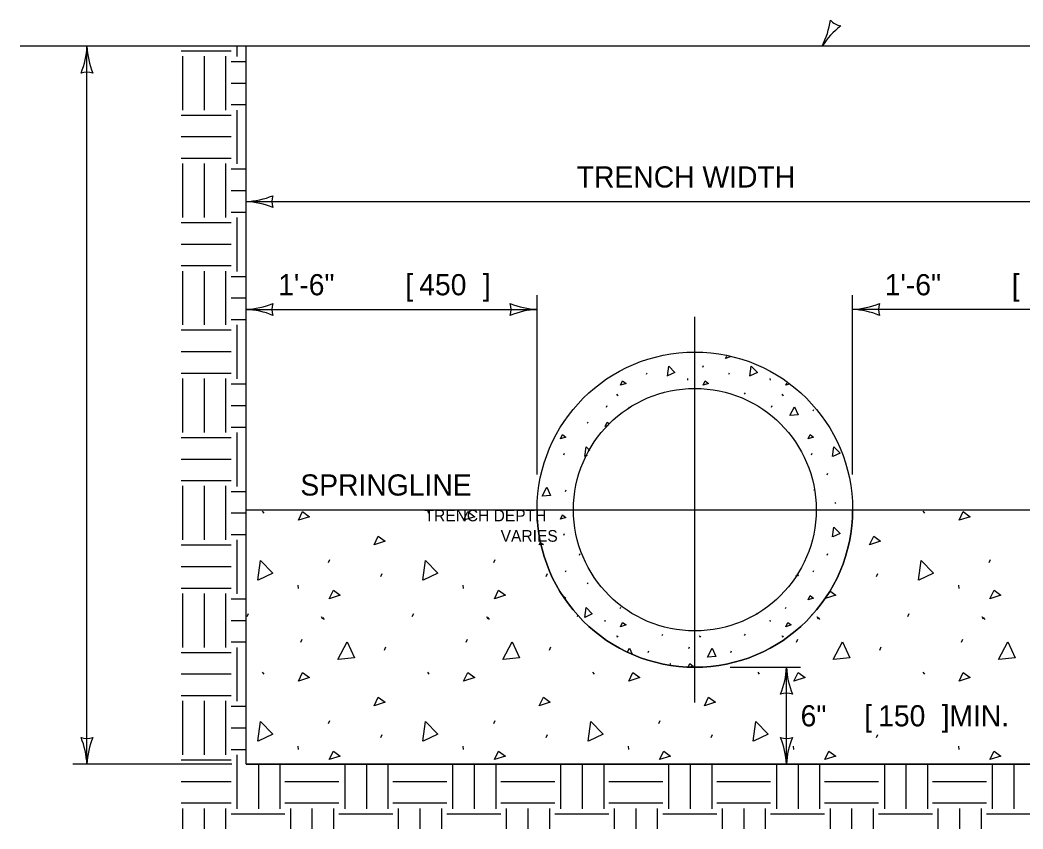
# Model space of a CAD drawing. Extents: x 49977.1 to 50021, y 49987.6 to 50011.4.
# Drawn here: x 49977.13 to 49982.31, y 49999.94 to 50004.11 of the extents above; entities that cross this region are included whole.
import ezdxf

# ---------------------------------------------------------------- set-up
doc = ezdxf.new("R2010")
doc.units = 0
for name, color, linetype in [('Level 1', 7, 'Continuous'), ('Level 2', 7, 'Continuous'), ('Level 3', 7, 'Continuous'), ('Level 5', 7, 'Continuous')]:
    doc.layers.add(name, color=color, linetype=linetype)

msp = doc.modelspace()

# ---------------------------------------------------------------- linework, layer by layer
at = {"layer": 'Level 1'}
for p, q in [((49984.0926, 50003.9758), (49977.1347, 50003.9758)), ((49978.2522, 50003.9758), (49978.2522, 50003.9231)), ((49978.2996, 50000.2744), (49978.2996, 50003.9758)), ((49977.966, 50003.9528), (49978.2223, 50003.9528)), ((49977.9719, 50003.925), (49977.9719, 50003.6471)), ((49978.0832, 50003.925), (49978.0832, 50003.6471)), ((49978.1945, 50003.925), (49978.1945, 50003.6471)), ((49978.2223, 50003.8972), (49978.2996, 50003.8972)), ((49978.2223, 50003.786), (49978.2996, 50003.786)), ((49978.2223, 50003.6749), (49978.2996, 50003.6749)), ((49978.2522, 50003.6471), (49978.2522, 50003.3691)), ((49977.966, 50003.6212), (49978.2223, 50003.6212)), ((49977.966, 50003.51), (49978.2223, 50003.51)), ((49977.966, 50003.3988), (49978.2223, 50003.3988)), ((49977.9719, 50003.371), (49977.9719, 50003.0931)), ((49978.0832, 50003.371), (49978.0832, 50003.0931)), ((49978.1945, 50003.371), (49978.1945, 50003.0931)), ((49978.2223, 50003.3432), (49978.2996, 50003.3432)), ((49978.2223, 50003.2321), (49978.2996, 50003.2321)), ((49978.2223, 50003.1209), (49978.2996, 50003.1209)), ((49978.2522, 50003.0931), (49978.2522, 50002.8151)), ((49977.966, 50003.0672), (49978.2223, 50003.0672)), ((49977.966, 50002.956), (49978.2223, 50002.956)), ((49977.966, 50002.8448), (49978.2223, 50002.8448)), ((49977.9719, 50002.817), (49977.9719, 50002.5391)), ((49978.0832, 50002.817), (49978.0832, 50002.5391)), ((49978.1945, 50002.817), (49978.1945, 50002.5391)), ((49978.2223, 50002.7892), (49978.2996, 50002.7892)), ((49978.2223, 50002.6781), (49978.2996, 50002.6781)), ((49978.2223, 50002.5669), (49978.2996, 50002.5669)), ((49977.966, 50002.5132), (49978.2223, 50002.5132)), ((49978.2522, 50002.5391), (49978.2522, 50002.2611)), ((49977.966, 50002.402), (49978.2223, 50002.402)), ((49980.6545, 50002.3213), (49980.6581, 50002.3293)), ((49977.966, 50002.2908), (49978.2223, 50002.2908)), ((49977.9719, 50002.263), (49977.9719, 50001.9851)), ((49978.0832, 50002.263), (49978.0832, 50001.9851)), ((49978.1945, 50002.263), (49978.1945, 50001.9851)), ((49980.3639, 50002.2849), (49980.3674, 50002.2929)), ((49980.5752, 50002.2626), (49980.5761, 50002.2546)), ((49980.7897, 50002.2849), (49980.7932, 50002.2929)), ((49981.001, 50002.2626), (49981.0019, 50002.2546)), ((49978.2223, 50002.2352), (49978.2996, 50002.2352)), ((49980.2101, 50002.1819), (49980.2137, 50002.1765)), ((49980.2137, 50002.1798), (49980.2172, 50002.1745)), ((49980.4473, 50002.1876), (49980.4483, 50002.1899)), ((49980.8705, 50002.1819), (49980.8741, 50002.1899)), ((49981.0616, 50002.1819), (49981.0652, 50002.1765)), ((49981.0652, 50002.1798), (49981.0688, 50002.1745)), ((49978.2223, 50002.1241), (49978.2996, 50002.1241)), ((49980.1577, 50002.116), (49980.1612, 50002.124)), ((49981.0092, 50002.116), (49981.0128, 50002.124)), ((49981.2243, 50002.0956), (49981.2279, 50002.1036)), ((49978.2223, 50002.0129), (49978.2996, 50002.0129)), ((49980.0581, 50002.0388), (49980.0617, 50002.0335)), ((49977.966, 50001.9592), (49978.2223, 50001.9592)), ((49978.2522, 50001.9851), (49978.2522, 50001.7071)), ((49977.966, 50001.848), (49978.2223, 50001.848)), ((49979.9381, 50001.8701), (49979.9417, 50001.8781)), ((49981.2154, 50001.8701), (49981.219, 50001.8781)), ((49977.966, 50001.7369), (49978.2223, 50001.7369)), ((49981.2963, 50001.7671), (49981.2999, 50001.775)), ((49977.9719, 50001.7091), (49977.9719, 50001.4311)), ((49978.0832, 50001.7091), (49978.0832, 50001.4311)), ((49978.1945, 50001.7091), (49978.1945, 50001.4311)), ((49978.2223, 50001.6813), (49978.2996, 50001.6813)), ((49979.947, 50001.6808), (49979.9505, 50001.6888)), ((49981.2274, 50001.6878), (49981.2279, 50001.6888)), ((49978.2996, 50000.2744), (49978.2996, 50001.5869)), ((49978.2996, 50001.5869), (49979.8004, 50001.5869)), ((49978.3836, 50001.5791), (49978.3907, 50001.5684)), ((49979.2352, 50001.5791), (49979.2423, 50001.5684)), ((49981.3354, 50001.624), (49981.339, 50001.6186)), ((49981.4269, 50001.5869), (49982.9277, 50001.5869)), ((49981.7898, 50001.5791), (49981.7969, 50001.5684)), ((49978.2223, 50001.5701), (49978.2996, 50001.5701)), ((49978.2223, 50001.4589), (49978.2996, 50001.4589)), ((49978.2522, 50001.4311), (49978.2522, 50001.1531)), ((49979.9381, 50001.4552), (49979.9417, 50001.4632)), ((49977.966, 50001.4052), (49978.2223, 50001.4052)), ((49979.8115, 50001.4059), (49979.818, 50001.4195)), ((49979.8203, 50001.4087), (49979.8115, 50001.4059)), ((49978.725, 50001.3145), (49978.7321, 50001.3304)), ((49979.5765, 50001.3145), (49979.5836, 50001.3304)), ((49980.019, 50001.3522), (49980.0225, 50001.3602)), ((49981.2963, 50001.3522), (49981.2999, 50001.3602)), ((49982.1312, 50001.3145), (49982.1383, 50001.3304)), ((49977.966, 50001.2941), (49978.2223, 50001.2941)), ((49979.947, 50001.266), (49979.9505, 50001.274)), ((49981.2243, 50001.266), (49981.2279, 50001.274)), ((49978.9952, 50001.2416), (49979.0023, 50001.2576)), ((49979.8467, 50001.2416), (49979.8538, 50001.2576)), ((49981.5498, 50001.2416), (49981.5569, 50001.2576)), ((49977.966, 50001.1829), (49978.2223, 50001.1829)), ((49978.5663, 50001.197), (49978.5681, 50001.181)), ((49979.4178, 50001.197), (49979.4196, 50001.181)), ((49980.0581, 50001.2092), (49980.0617, 50001.2038)), ((49981.9725, 50001.197), (49981.9743, 50001.181)), ((49977.9719, 50001.1551), (49977.9719, 50000.8771)), ((49978.0832, 50001.1551), (49978.0832, 50000.8771)), ((49978.1945, 50001.1551), (49978.1945, 50000.8771)), ((49978.2223, 50001.1273), (49978.2996, 50001.1273)), ((49980.2288, 50001.0768), (49980.2323, 50001.0848)), ((49981.0803, 50001.0768), (49981.0839, 50001.0848)), ((49978.2223, 50001.0161), (49978.2996, 50001.0161)), ((49978.3054, 50001.0356), (49978.3125, 50001.0516)), ((49978.6876, 50001.0356), (49978.6947, 50001.025)), ((49978.6947, 50001.0316), (49978.7018, 50001.0209)), ((49979.1569, 50001.0356), (49979.1641, 50001.0516)), ((49979.5392, 50001.0356), (49979.5463, 50001.025)), ((49979.5463, 50001.0316), (49979.5534, 50001.0209)), ((49980.0085, 50001.0356), (49980.0111, 50001.0415)), ((49980.1494, 50001.0181), (49980.1503, 50001.0101)), ((49981.001, 50001.0181), (49981.0019, 50001.0101)), ((49981.2176, 50001.0454), (49981.219, 50001.0484)), ((49981.2423, 50001.0356), (49981.2494, 50001.025)), ((49981.2494, 50001.0316), (49981.2565, 50001.0209)), ((49981.7116, 50001.0356), (49981.7187, 50001.0516)), ((49982.0938, 50001.0356), (49982.1009, 50001.025)), ((49982.1009, 50001.0316), (49982.108, 50001.0209)), ((49978.2223, 50000.9049), (49978.2996, 50000.9049)), ((49978.5827, 50000.904), (49978.5898, 50000.92)), ((49979.4343, 50000.904), (49979.4414, 50000.92)), ((49980.2101, 50000.9374), (49980.2137, 50000.9321)), ((49980.2137, 50000.9354), (49980.2172, 50000.9301)), ((49980.4448, 50000.9374), (49980.4483, 50000.9454)), ((49980.6359, 50000.9374), (49980.6394, 50000.9321)), ((49980.6394, 50000.9354), (49980.643, 50000.9301)), ((49980.8705, 50000.9374), (49980.8741, 50000.9454)), ((49981.0616, 50000.9374), (49981.0652, 50000.9321)), ((49981.0652, 50000.9354), (49981.0688, 50000.9301)), ((49981.1374, 50000.904), (49981.1445, 50000.92)), ((49981.9889, 50000.904), (49981.996, 50000.92)), ((49978.2522, 50000.8771), (49978.2522, 50000.5991)), ((49979.0129, 50000.8631), (49979.0201, 50000.8791)), ((49979.8645, 50000.8631), (49979.8716, 50000.8791)), ((49980.3728, 50000.8512), (49980.3763, 50000.8592)), ((49980.5834, 50000.8716), (49980.587, 50000.8796)), ((49980.7985, 50000.8512), (49980.8021, 50000.8592)), ((49981.5676, 50000.8631), (49981.5747, 50000.8791)), ((49977.966, 50000.8512), (49978.2223, 50000.8512)), ((49978.3836, 50000.7495), (49978.3907, 50000.7388)), ((49979.2352, 50000.7495), (49979.2423, 50000.7388)), ((49980.0867, 50000.7495), (49980.0938, 50000.7388)), ((49980.4839, 50000.7943), (49980.4874, 50000.789)), ((49980.9383, 50000.7495), (49980.9454, 50000.7388)), ((49981.7898, 50000.7495), (49981.7969, 50000.7388)), ((49977.966, 50000.7401), (49978.2223, 50000.7401)), ((49977.966, 50000.6289), (49978.2223, 50000.6289)), ((49977.9719, 50000.6011), (49977.9719, 50000.3231)), ((49978.0832, 50000.6011), (49978.0832, 50000.3231)), ((49978.1945, 50000.6011), (49978.1945, 50000.3231)), ((49978.2223, 50000.5733), (49978.2996, 50000.5733)), ((49978.725, 50000.4848), (49978.7321, 50000.5008)), ((49979.5765, 50000.4848), (49979.5836, 50000.5008)), ((49980.4281, 50000.4848), (49980.4352, 50000.5008)), ((49978.2223, 50000.4621), (49978.2996, 50000.4621)), ((49978.9952, 50000.412), (49979.0023, 50000.428)), ((49979.8467, 50000.412), (49979.8538, 50000.428)), ((49980.6983, 50000.412), (49980.7054, 50000.428)), ((49981.5498, 50000.412), (49981.5569, 50000.428)), ((49978.2223, 50000.3509), (49978.2996, 50000.3509)), ((49978.5663, 50000.3674), (49978.5681, 50000.3514)), ((49979.4178, 50000.3674), (49979.4196, 50000.3514)), ((49980.2694, 50000.3674), (49980.2712, 50000.3514)), ((49981.1209, 50000.3674), (49981.1227, 50000.3514)), ((49981.9725, 50000.3674), (49981.9743, 50000.3514)), ((49977.966, 50000.2972), (49978.2223, 50000.2972)), ((49978.2522, 50000.3231), (49978.2522, 50000.0451)), ((49982.9277, 50000.2744), (49978.2996, 50000.2744)), ((49978.2996, 50000.2744), (49982.9277, 50000.2744)), ((49978.3635, 50000.2744), (49978.3635, 50000.0451)), ((49978.4748, 50000.2744), (49978.4748, 50000.0451)), ((49978.8087, 50000.2744), (49978.8087, 50000.0451)), ((49978.92, 50000.2744), (49978.92, 50000.0451)), ((49979.0313, 50000.2744), (49979.0313, 50000.0451)), ((49979.3651, 50000.2744), (49979.3651, 50000.0451)), ((49979.4764, 50000.2744), (49979.4764, 50000.0451)), ((49979.5877, 50000.2744), (49979.5877, 50000.0451)), ((49979.9216, 50000.2744), (49979.9216, 50000.0451)), ((49980.0329, 50000.2744), (49980.0329, 50000.0451)), ((49980.1442, 50000.2744), (49980.1442, 50000.0451)), ((49980.478, 50000.2744), (49980.478, 50000.0451)), ((49980.5893, 50000.2744), (49980.5893, 50000.0451)), ((49980.7006, 50000.2744), (49980.7006, 50000.0451)), ((49981.0345, 50000.2744), (49981.0345, 50000.0451)), ((49981.1458, 50000.2744), (49981.1458, 50000.0451)), ((49981.2571, 50000.2744), (49981.2571, 50000.0451)), ((49981.5909, 50000.2744), (49981.5909, 50000.0451)), ((49981.7022, 50000.2744), (49981.7022, 50000.0451)), ((49981.8135, 50000.2744), (49981.8135, 50000.0451)), ((49982.1474, 50000.2744), (49982.1474, 50000.0451)), ((49982.2587, 50000.2744), (49982.2587, 50000.0451)), ((49977.966, 50000.1861), (49978.2223, 50000.1861)), ((49978.5006, 50000.1861), (49978.7788, 50000.1861)), ((49979.057, 50000.1861), (49979.3352, 50000.1861)), ((49979.6135, 50000.1861), (49979.8917, 50000.1861)), ((49980.1699, 50000.1861), (49980.4482, 50000.1861)), ((49980.7264, 50000.1861), (49981.0046, 50000.1861)), ((49981.2828, 50000.1861), (49981.5611, 50000.1861)), ((49981.8393, 50000.1861), (49982.1175, 50000.1861)), ((49977.966, 50000.0749), (49978.2223, 50000.0749)), ((49977.9719, 50000.0471), (49977.9719, 49999.9411)), ((49978.0832, 50000.0471), (49978.0832, 49999.9411)), ((49978.1945, 50000.0471), (49978.1945, 49999.9411)), ((49978.5006, 50000.0749), (49978.7788, 50000.0749)), ((49978.5284, 50000.0471), (49978.5284, 49999.9411)), ((49978.6397, 50000.0471), (49978.6397, 49999.9411)), ((49978.751, 50000.0471), (49978.751, 49999.9411)), ((49979.057, 50000.0749), (49979.3352, 50000.0749)), ((49979.0848, 50000.0471), (49979.0848, 49999.9411)), ((49979.1961, 50000.0471), (49979.1961, 49999.9411)), ((49979.3074, 50000.0471), (49979.3074, 49999.9411)), ((49979.6135, 50000.0749), (49979.8917, 50000.0749)), ((49979.6413, 50000.0471), (49979.6413, 49999.9411)), ((49979.7526, 50000.0471), (49979.7526, 49999.9411)), ((49979.8639, 50000.0471), (49979.8639, 49999.9411)), ((49980.1699, 50000.0749), (49980.4482, 50000.0749)), ((49980.1978, 50000.0471), (49980.1978, 49999.9411)), ((49980.309, 50000.0471), (49980.309, 49999.9411)), ((49980.4203, 50000.0471), (49980.4203, 49999.9411)), ((49980.7264, 50000.0749), (49981.0046, 50000.0749)), ((49980.7542, 50000.0471), (49980.7542, 49999.9411)), ((49980.8655, 50000.0471), (49980.8655, 49999.9411)), ((49980.9768, 50000.0471), (49980.9768, 49999.9411)), ((49981.2828, 50000.0749), (49981.5611, 50000.0749)), ((49981.3107, 50000.0471), (49981.3107, 49999.9411)), ((49981.422, 50000.0471), (49981.422, 49999.9411)), ((49981.5332, 50000.0471), (49981.5332, 49999.9411)), ((49981.8393, 50000.0749), (49982.1175, 50000.0749)), ((49981.8671, 50000.0471), (49981.8671, 49999.9411)), ((49981.9784, 50000.0471), (49981.9784, 49999.9411)), ((49982.0897, 50000.0471), (49982.0897, 49999.9411)), ((49978.2223, 50000.0193), (49978.5006, 50000.0193)), ((49978.7788, 50000.0193), (49979.057, 50000.0193)), ((49979.3352, 50000.0193), (49979.6135, 50000.0193)), ((49979.8917, 50000.0193), (49980.1699, 50000.0193)), ((49980.4482, 50000.0193), (49980.7264, 50000.0193)), ((49981.0046, 50000.0193), (49981.2828, 50000.0193)), ((49981.5611, 50000.0193), (49981.8393, 50000.0193)), ((49982.1175, 50000.0193), (49982.3958, 50000.0193))]:
    msp.add_line(p, q, dxfattribs=at)
for points in [[(49980.7721, 50002.367), (49980.7778, 50002.3789)], [(49980.7959, 50002.3745), (49980.7721, 50002.367)], [(49980.472, 50002.2757), (49980.4791, 50002.3264), (49980.5109, 50002.2936), (49980.4728, 50002.276)], [(49980.8978, 50002.2757), (49980.9048, 50002.3264), (49980.9367, 50002.2936), (49980.8986, 50002.276)], [(49980.2306, 50002.228), (49980.2412, 50002.2502), (49980.259, 50002.2369), (49980.2306, 50002.228)], [(49980.6563, 50002.228), (49980.667, 50002.2502), (49980.6848, 50002.2369), (49980.6563, 50002.228)], [(49981.0821, 50002.228), (49981.0886, 50002.2415)], [(49981.0993, 50002.2334), (49981.0821, 50002.228)], [(49980.2712, 50002.1065), (49980.2768, 50002.1169), (49980.2789, 50002.1122)], [(49981.1043, 50002.0716), (49981.1283, 50002.1169), (49981.147, 50002.0752), (49981.1052, 50002.0716)], [(49980.1514, 50002.0157), (49980.1621, 50002.0379), (49980.1735, 50002.0293)], [(49980.166, 50002.0202), (49980.1514, 50002.0157)], [(49979.9205, 50001.9522), (49979.9312, 50001.9744), (49979.9489, 50001.9611), (49979.9205, 50001.9522)], [(49981.1978, 50001.9522), (49981.2085, 50001.9744), (49981.2263, 50001.9611), (49981.1978, 50001.9522)], [(49980.0462, 50001.8609), (49980.0533, 50001.9116), (49980.0717, 50001.8926)], [(49981.3236, 50001.8609), (49981.3306, 50001.9116), (49981.3624, 50001.8788), (49981.3244, 50001.8612)], [(49980.0589, 50001.8667), (49980.0471, 50001.8612)], [(49979.827, 50001.6568), (49979.851, 50001.7021), (49979.8697, 50001.6604), (49979.8279, 50001.6568)], [(49978.5703, 50001.5329), (49978.5916, 50001.5773), (49978.6272, 50001.5507), (49978.5703, 50001.5329)], [(49979.4218, 50001.5329), (49979.4432, 50001.5773), (49979.4787, 50001.5507), (49979.4218, 50001.5329)], [(49981.9765, 50001.5329), (49981.9978, 50001.5773), (49982.0334, 50001.5507), (49981.9765, 50001.5329)], [(49979.9205, 50001.5374), (49979.9312, 50001.5596), (49979.9489, 50001.5463), (49979.9205, 50001.5374)], [(49981.3236, 50001.4461), (49981.3306, 50001.4968), (49981.3624, 50001.464), (49981.3244, 50001.4464)], [(49978.96, 50001.4059), (49978.9813, 50001.4504), (49979.0169, 50001.4237), (49978.96, 50001.4059)], [(49981.5146, 50001.4059), (49981.5359, 50001.4504), (49981.5715, 50001.4237), (49981.5146, 50001.4059)], [(49979.8229, 50001.415), (49979.8332, 50001.4073), (49979.8254, 50001.4049)], [(49978.3599, 50001.2233), (49978.374, 50001.3248), (49978.4376, 50001.2591), (49978.3616, 50001.2239)], [(49979.2114, 50001.2233), (49979.2255, 50001.3248), (49979.2892, 50001.2591), (49979.2131, 50001.2239)], [(49981.7661, 50001.2233), (49981.7802, 50001.3248), (49981.8438, 50001.2591), (49981.7678, 50001.2239)], [(49981.1411, 50001.2587), (49981.147, 50001.2456), (49981.132, 50001.2443)], [(49978.7285, 50001.128), (49978.7499, 50001.1724), (49978.7854, 50001.1457), (49978.7285, 50001.128)], [(49979.5801, 50001.128), (49979.6014, 50001.1724), (49979.637, 50001.1457), (49979.5801, 50001.128)], [(49981.3103, 50001.168), (49981.3401, 50001.1457), (49981.285, 50001.1286)], [(49982.1347, 50001.128), (49982.1561, 50001.1724), (49982.1916, 50001.1457), (49982.1347, 50001.128)], [(49979.9379, 50001.1397), (49979.9489, 50001.1315), (49979.9451, 50001.1303)], [(49981.1978, 50001.1226), (49981.2085, 50001.1448), (49981.2263, 50001.1315), (49981.1978, 50001.1226)], [(49980.0462, 50001.0312), (49980.0533, 50001.082), (49980.0851, 50001.0492), (49980.0471, 50001.0315)], [(49980.8978, 50001.0312), (49980.8981, 50001.0335)], [(49980.9321, 50001.0539), (49980.9367, 50001.0492), (49980.8986, 50001.0315)], [(49980.2306, 50000.9836), (49980.2412, 50001.0058), (49980.259, 50000.9925), (49980.2306, 50000.9836)], [(49981.0821, 50000.9836), (49981.0928, 50001.0058), (49981.1105, 50000.9925), (49981.0821, 50000.9836)], [(49978.773, 50000.8152), (49978.821, 50000.9057), (49978.8583, 50000.8223), (49978.7747, 50000.8152)], [(49979.6245, 50000.8152), (49979.6725, 50000.9057), (49979.7098, 50000.8223), (49979.6263, 50000.8152)], [(49981.3276, 50000.8152), (49981.3756, 50000.9057), (49981.4129, 50000.8223), (49981.3294, 50000.8152)], [(49982.1792, 50000.8152), (49982.2272, 50000.9057), (49982.2645, 50000.8223), (49982.1809, 50000.8152)], [(49980.2671, 50000.8541), (49980.2768, 50000.8725), (49980.2906, 50000.8416)], [(49980.6786, 50000.8272), (49980.7025, 50000.8725), (49980.7212, 50000.8308), (49980.6794, 50000.8272)], [(49980.5803, 50000.7776), (49980.5879, 50000.7935), (49980.6056, 50000.7801), (49980.5933, 50000.7763)], [(49978.5703, 50000.7033), (49978.5916, 50000.7477), (49978.6272, 50000.721), (49978.5703, 50000.7033)], [(49979.4218, 50000.7033), (49979.4432, 50000.7477), (49979.4787, 50000.721), (49979.4218, 50000.7033)], [(49980.2734, 50000.7033), (49980.2947, 50000.7477), (49980.3303, 50000.721), (49980.2734, 50000.7033)], [(49981.1249, 50000.7033), (49981.1463, 50000.7477), (49981.1818, 50000.721), (49981.1249, 50000.7033)], [(49981.9765, 50000.7033), (49981.9978, 50000.7477), (49982.0334, 50000.721), (49981.9765, 50000.7033)], [(49978.96, 50000.5763), (49978.9813, 50000.6207), (49979.0169, 50000.5941), (49978.96, 50000.5763)], [(49979.8115, 50000.5763), (49979.8328, 50000.6207), (49979.8684, 50000.5941), (49979.8115, 50000.5763)], [(49980.6631, 50000.5763), (49980.6844, 50000.6207), (49980.72, 50000.5941), (49980.6631, 50000.5763)], [(49978.3599, 50000.3936), (49978.374, 50000.4951), (49978.4376, 50000.4295), (49978.3616, 50000.3942)], [(49979.2114, 50000.3936), (49979.2255, 50000.4951), (49979.2892, 50000.4295), (49979.2131, 50000.3942)], [(49980.063, 50000.3936), (49980.0771, 50000.4951), (49980.1407, 50000.4295), (49980.0647, 50000.3942)], [(49980.9145, 50000.3936), (49980.9286, 50000.4951), (49980.9923, 50000.4295), (49980.9162, 50000.3942)], [(49978.7285, 50000.2983), (49978.7499, 50000.3427), (49978.7854, 50000.3161), (49978.7285, 50000.2983)], [(49979.5801, 50000.2983), (49979.6014, 50000.3427), (49979.637, 50000.3161), (49979.5801, 50000.2983)], [(49980.4316, 50000.2983), (49980.453, 50000.3427), (49980.4885, 50000.3161), (49980.4316, 50000.2983)], [(49981.2832, 50000.2983), (49981.3045, 50000.3427), (49981.3401, 50000.3161), (49981.2832, 50000.2983)], [(49982.1347, 50000.2983), (49982.1561, 50000.3427), (49982.1916, 50000.3161), (49982.1347, 50000.2983)]]:
    msp.add_lwpolyline(points, dxfattribs=at)
for major_axis in [(0.8133, 0), (0.6256, 0)]:
    msp.add_ellipse((49980.6137, 50001.5869), major_axis=major_axis, ratio=0.999067, dxfattribs=at)
msp.add_ellipse((49980.6137, 50001.5869), major_axis=(0.8133, 0), ratio=0.999067, start_param=3.141593, end_param=6.283185, dxfattribs=at)
at = {"layer": 'Level 3'}
for p, q in [((49977.4796, 50000.2744), (49977.4796, 50003.9758)), ((49978.2996, 50003.1749), (49982.9277, 50003.1749)), ((49979.8004, 50001.7687), (49979.8004, 50002.692)), ((49981.4269, 50001.7687), (49981.4269, 50002.692)), ((49978.2996, 50002.6192), (49979.8004, 50002.6192)), ((49982.9277, 50002.6192), (49981.4269, 50002.6192)), ((49980.7956, 50000.7744), (49981.159, 50000.7744)), ((49981.0862, 50000.2744), (49981.0862, 50000.7744)), ((49978.2268, 50000.2744), (49977.4068, 50000.2744))]:
    msp.add_line(p, q, dxfattribs=at)
for centre, major_axis, start_param, end_param in [((49980.8927, 50004.1697), (0.424, 0), 5.80784, 6.143814), ((49981.3866, 50004.1776), (-0.0997, 0), 0.734369, 1.357842), ((49981.6113, 50003.7591), (-0.4046, 0), 5.365028, 5.717296), ((49977.0753, 50003.9925), (0.4046, 0), 5.889718, 6.241987), ((49977.9031, 50003.9967), (-0.424, 0), 0.049346, 0.385319), ((49977.4796, 50003.7427), (-0.0997, 0), 4.400653, 5.024125), ((49978.2787, 50003.598), (0.424, 0), 4.761735, 5.097708), ((49978.533, 50003.1749), (-0.0997, 0), 5.971449, 6.594922), ((49978.283, 50002.771), (-0.4046, 0), 4.318922, 4.671191), ((49978.2787, 50003.0423), (0.424, 0), 4.761735, 5.097708), ((49978.283, 50002.2153), (-0.4046, 0), 4.318922, 4.671191), ((49978.533, 50002.6192), (-0.0997, 0), 5.971449, 6.594922), ((49979.817, 50003.0231), (0.4046, 0), 4.318922, 4.671191), ((49979.567, 50002.6192), (0.0997, 0), 5.971449, 6.594922), ((49979.8213, 50002.1961), (-0.424, 0), 4.761735, 5.097708), ((49981.406, 50003.0423), (0.424, 0), 4.761735, 5.097708), ((49981.4103, 50002.2153), (-0.4046, 0), 4.318922, 4.671191), ((49981.6603, 50002.6192), (-0.0997, 0), 5.971449, 6.594922), ((49980.682, 50000.791), (0.4046, 0), 5.889718, 6.241987), ((49981.5097, 50000.7953), (-0.424, 0), 0.049346, 0.385319), ((49981.0862, 50000.5413), (-0.0997, 0), 4.400653, 5.024125), ((49977.4796, 50000.5075), (0.0997, 0), 4.400653, 5.024125), ((49977.0561, 50000.2535), (0.424, 0), 0.049346, 0.385319), ((49977.8838, 50000.2577), (-0.4046, 0), 5.889718, 6.241987), ((49981.0862, 50000.5075), (0.0997, 0), 4.400653, 5.024125), ((49980.6627, 50000.2535), (0.424, 0), 0.049346, 0.385319), ((49981.4905, 50000.2577), (-0.4046, 0), 5.889718, 6.241987)]:
    msp.add_ellipse(centre, major_axis=major_axis, ratio=0.999067, start_param=start_param, end_param=end_param, dxfattribs=at)
at = {"layer": 'Level 5'}
for p, q in [((49980.6137, 50000.5926), (49980.6137, 50002.5812)), ((49979.6184, 50001.5869), (49981.6089, 50001.5869))]:
    msp.add_line(p, q, dxfattribs=at)

# ---------------------------------------------------------------- texts
at = {"layer": 'Level 2'}
for s, height, p in [('TRENCH WIDTH', 0.109091, (49980.0047, 50003.2476)), ('1\'-6" ', 0.10909, (49978.4654, 50002.692)), ('[', 0.1091, (49979.1205, 50002.692)), ('450', 0.10909, (49979.1927, 50002.692)), (']', 0.1091, (49979.5203, 50002.692)), ('1\'-6" ', 0.10909, (49981.5927, 50002.692)), ('[', 0.1091, (49982.2478, 50002.692)), ('SPRINGLINE', 0.10909, (49978.5797, 50001.6596)), ('TRENCH DEPTH', 0.06, (49979.2198, 50001.5267)), ('VARIES', 0.06, (49979.6125, 50001.4217)), ('6" ', 0.10909, (49981.159, 50000.4698)), ('[', 0.1091, (49981.4866, 50000.4698)), ('150', 0.10909, (49981.5588, 50000.4698)), (']', 0.1091, (49981.8864, 50000.4698)), (' MIN.', 0.10909, (49981.8855, 50000.4698))]:
    msp.add_text(s, height=height, dxfattribs=at).set_placement(p)

doc.saveas('drawing.dxf')
